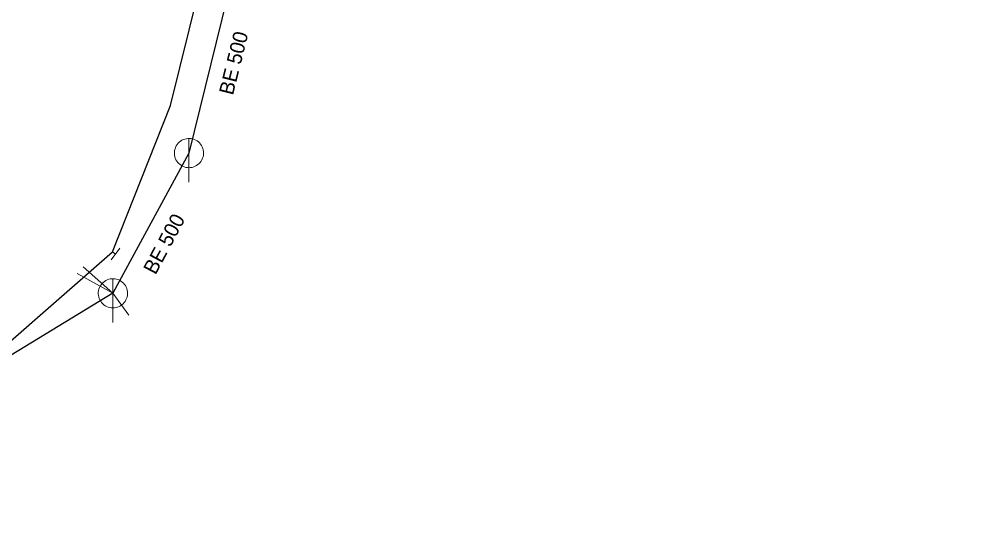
# Model space of a CAD drawing. Extents: x -687013 to -686506, y -973869 to -973672.
# Drawn here: x -686949.6 to -686884.2, y -973790.3 to -973756 of the extents above; entities that cross this region are included whole.
import ezdxf

# ---------------------------------------------------------------- set-up
doc = ezdxf.new("R2010")
doc.units = 0
doc.header["$LTSCALE"] = 0.4
doc.layers.add('1', color=7, linetype='Continuous')
for name, color, linetype, lineweight in [('11', 7, 'Continuous', 13), ('14', 7, 'Continuous', 25), ('17', 7, 'Continuous', 25), ('22', 7, 'Continuous', 13), ('34', 7, 'Continuous', 13)]:
    doc.layers.add(name, color=color, linetype=linetype, lineweight=lineweight)

msp = doc.modelspace()

# ---------------------------------------------------------------- linework, layer by layer
at = {"layer": '11'}
for p in [(-686945.2, -973772.964), (-686945.605, -973773.428), (-686942.069, -973776.269)]:
    msp.add_line(p, (-686943.166, -973774.771), dxfattribs=at)
at = {"layer": '14'}
for p, q in [((-686934.37, -973750.579), (-686937.96, -973765.178)), ((-686937.96, -973765.178), (-686943.166, -973774.771)), ((-686943.166, -973774.771), (-686961.432, -973785.892))]:
    msp.add_line(p, q, dxfattribs=at)
at = {"layer": '14', "lineweight": 13}
msp.add_line((-686943.195, -973771.934), (-686942.989, -973772.089), dxfattribs=at)
at = {"layer": '17'}
msp.add_lwpolyline([(-686976.761, -973790.276), (-686962.561, -973784.848), (-686950.728, -973778.526), (-686943.195, -973771.934), (-686939.23, -973761.912), (-686935.397, -973746.442), (-686925.984, -973737.294), (-686915.07, -973732.61), (-686899.151, -973729.811), (-686884.189, -973728.62)], dxfattribs=at)
at = {"layer": '22'}
for p, q in [((-686937.96, -973767.178), (-686937.959, -973764.178)), ((-686943.166, -973776.771), (-686943.165, -973773.771))]:
    msp.add_line(p, q, dxfattribs=at)
for points in [[(-686936.96, -973765.178), (-686936.965, -973765.069), (-686936.983, -973764.961), (-686937.013, -973764.855), (-686937.053, -973764.754), (-686937.105, -973764.657), (-686937.167, -973764.567), (-686937.239, -973764.484), (-686937.319, -973764.41), (-686937.407, -973764.344), (-686937.501, -973764.289), (-686937.601, -973764.244), (-686937.706, -973764.211), (-686937.813, -973764.189), (-686937.922, -973764.179), (-686938.032, -973764.181), (-686938.14, -973764.195), (-686938.247, -973764.22), (-686938.35, -973764.257), (-686938.448, -973764.306), (-686938.54, -973764.364), (-686938.626, -973764.433), (-686938.703, -973764.51), (-686938.772, -973764.596), (-686938.831, -973764.688), (-686938.879, -973764.786), (-686938.916, -973764.889), (-686938.942, -973764.996), (-686938.956, -973765.104), (-686938.959, -973765.214), (-686938.949, -973765.323), (-686938.928, -973765.43), (-686938.894, -973765.534), (-686938.85, -973765.634), (-686938.795, -973765.729), (-686938.729, -973765.817), (-686938.655, -973765.897), (-686938.572, -973765.969), (-686938.482, -973766.031), (-686938.386, -973766.083), (-686938.284, -973766.124), (-686938.179, -973766.154), (-686938.071, -973766.172), (-686937.961, -973766.178), (-686937.852, -973766.172), (-686937.744, -973766.154), (-686937.639, -973766.125), (-686937.537, -973766.084), (-686937.44, -973766.032), (-686937.35, -973765.97), (-686937.267, -973765.899), (-686937.192, -973765.819), (-686937.127, -973765.731), (-686937.071, -973765.637), (-686937.027, -973765.537), (-686936.993, -973765.433), (-686936.971, -973765.325), (-686936.961, -973765.216)], [(-686942.166, -973774.771), (-686942.171, -973774.662), (-686942.189, -973774.554), (-686942.219, -973774.448), (-686942.259, -973774.347), (-686942.311, -973774.25), (-686942.373, -973774.16), (-686942.445, -973774.077), (-686942.525, -973774.003), (-686942.613, -973773.937), (-686942.707, -973773.882), (-686942.807, -973773.837), (-686942.912, -973773.804), (-686943.019, -973773.782), (-686943.128, -973773.772), (-686943.238, -973773.774), (-686943.346, -973773.788), (-686943.453, -973773.813), (-686943.556, -973773.85), (-686943.654, -973773.899), (-686943.746, -973773.957), (-686943.832, -973774.026), (-686943.909, -973774.103), (-686943.978, -973774.189), (-686944.037, -973774.281), (-686944.085, -973774.379), (-686944.122, -973774.482), (-686944.148, -973774.589), (-686944.162, -973774.697), (-686944.165, -973774.807), (-686944.155, -973774.916), (-686944.134, -973775.023), (-686944.1, -973775.127), (-686944.056, -973775.227), (-686944.001, -973775.322), (-686943.935, -973775.41), (-686943.861, -973775.49), (-686943.778, -973775.562), (-686943.688, -973775.624), (-686943.592, -973775.676), (-686943.49, -973775.717), (-686943.385, -973775.747), (-686943.277, -973775.765), (-686943.167, -973775.771), (-686943.058, -973775.765), (-686942.95, -973775.747), (-686942.845, -973775.718), (-686942.743, -973775.677), (-686942.646, -973775.625), (-686942.556, -973775.563), (-686942.473, -973775.492), (-686942.398, -973775.412), (-686942.333, -973775.324), (-686942.277, -973775.23), (-686942.233, -973775.13), (-686942.199, -973775.026), (-686942.177, -973774.918), (-686942.167, -973774.809)]]:
    msp.add_lwpolyline(points, close=True, dxfattribs=at)
at = {"layer": '34'}
msp.add_line((-686942.688, -973771.689), (-686943.29, -973772.488), dxfattribs=at)

# ---------------------------------------------------------------- texts
at = {"layer": '1'}
for rotation, p in [(76, (-686934.952, -973761.265)), (62, (-686940.248, -973773.558))]:
    msp.add_text('BE 500', height=1, rotation=rotation, dxfattribs=at).set_placement(p)

doc.saveas('drawing.dxf')
